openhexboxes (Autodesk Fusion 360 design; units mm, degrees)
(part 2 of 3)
sketch "Skizze8" plane through (0, 0, 50) normal (0, 0, 1) x axis (1, 0, 0)
  line L1 (-23.6181, -113.2077) -> (-22.5788, -113.2077)
  line L2 (-20.4382, -105) -> (-24.3975, -111.8577)
  line L3 (-24.3975, -98.1423) -> (-20.4382, -105)
  line L4 (-25.7831, -99.0423) -> (-25.2635, -98.1423)
  line L5 (-33.342, -88.65) -> (-27.342, -99.0423)
  line L6 (-28.0592, -87.3) -> (-32.5626, -87.3)
  line L7 (-33.6262, -76.1577) -> (-27.6262, -86.55)
  line L8 (-35.0119, -77.0577) -> (-34.4922, -76.1577)
  line L9 (-40.53, -70.2) -> (-36.5707, -77.0577)
  line L10 (-48.4486, -70.2) -> (-40.53, -70.2)
  line L11 (-48.362, -71.85) -> (-48.8816, -70.95)
  line L12 (-61.1414, -73.2) -> (-49.1414, -73.2)
  line L13 (-59.6692, -67.95) -> (-61.9208, -71.85)
  line L14 (-72.1022, -67.2) -> (-60.1022, -67.2)
  line L15 (-72.0156, -68.85) -> (-72.5352, -67.95)
  line L16 (-80.7136, -70.2) -> (-72.795, -70.2)
  line L17 (-84.6729, -77.0577) -> (-80.7136, -70.2)
  line L18 (-83.2006, -77.8077) -> (-84.2398, -77.8077)
  line L19 (-88.4212, -89.55) -> (-82.4212, -79.1577)
  line L20 (-92.2317, -85.65) -> (-89.98, -89.55)
  line L21 (-99.0977, -96.0423) -> (-93.0977, -85.65)
  line L22 (-97.6255, -96.7923) -> (-98.6647, -96.7923)
  line L23 (-100.8054, -105) -> (-96.8461, -98.1423)
  line L24 (-96.8461, -111.8577) -> (-100.8054, -105)
  line L25 (-95.4604, -110.9577) -> (-95.98, -111.8577)
  line L26 (-87.9016, -121.35) -> (-93.9016, -110.9577)
  line L27 (-93.1843, -122.7) -> (-88.681, -122.7)
  line L28 (-87.6173, -133.8423) -> (-93.6173, -123.45)
  line L29 (-86.2317, -132.9423) -> (-86.7513, -133.8423)
  line L30 (-80.7136, -139.8) -> (-84.6729, -132.9423)
  line L31 (-72.795, -139.8) -> (-80.7136, -139.8)
  line L32 (-72.8816, -138.15) -> (-72.362, -139.05)
  line L33 (-60.1022, -136.8) -> (-72.1022, -136.8)
  line L34 (-61.5744, -142.05) -> (-59.3227, -138.15)
  line L35 (-49.1414, -142.8) -> (-61.1414, -142.8)
  line L36 (-49.228, -141.15) -> (-48.7084, -142.05)
  line L37 (-40.53, -139.8) -> (-48.4486, -139.8)
  line L38 (-36.5707, -132.9423) -> (-40.53, -139.8)
  line L39 (-38.0429, -132.1923) -> (-37.0037, -132.1923)
  line L40 (-32.8224, -120.45) -> (-38.8224, -130.8423)
  line L41 (-29.0119, -124.35) -> (-31.2635, -120.45)
  line L42 (-22.1458, -113.9577) -> (-28.1458, -124.35)
  line L43 (-100.8054, -105) -> (-20.4382, -105)
  line L44 (-80.7136, -139.8) -> (-40.53, -70.2)
  arc A1 centre (-23.6181, -112.3077) radius 0.9 clockwise from (-23.6181, -113.2077) to (-24.3975, -111.8577)
  arc A2 centre (-24.8305, -98.3923) radius 0.5 clockwise from (-25.2635, -98.1423) to (-24.3975, -98.1423)
  arc A3 centre (-26.5626, -98.5923) radius 0.9 clockwise from (-25.7831, -99.0423) to (-27.342, -99.0423)
  arc A4 centre (-32.5626, -88.2) radius 0.9 clockwise from (-33.342, -88.65) to (-32.5626, -87.3)
  arc A5 centre (-28.0592, -86.8) radius 0.5 clockwise from (-27.6262, -86.55) to (-28.0592, -87.3)
  arc A6 centre (-34.0592, -76.4077) radius 0.5 clockwise from (-34.4922, -76.1577) to (-33.6262, -76.1577)
  arc A7 centre (-35.7913, -76.6077) radius 0.9 clockwise from (-35.0119, -77.0577) to (-36.5707, -77.0577)
  arc A8 centre (-48.4486, -70.7) radius 0.5 clockwise from (-48.8816, -70.95) to (-48.4486, -70.2)
  arc A9 centre (-49.1414, -72.3) radius 0.9 clockwise from (-48.362, -71.85) to (-49.1414, -73.2)
  arc A10 centre (-61.1414, -72.3) radius 0.9 clockwise from (-61.1414, -73.2) to (-61.9208, -71.85)
  arc A11 centre (-60.1022, -67.7) radius 0.5 clockwise from (-60.1022, -67.2) to (-59.6692, -67.95)
  arc A12 centre (-72.1022, -67.7) radius 0.5 clockwise from (-72.5352, -67.95) to (-72.1022, -67.2)
  arc A13 centre (-72.795, -69.3) radius 0.9 clockwise from (-72.0156, -68.85) to (-72.795, -70.2)
  arc A14 centre (-84.2398, -77.3077) radius 0.5 clockwise from (-84.2398, -77.8077) to (-84.6729, -77.0577)
  arc A15 centre (-83.2006, -78.7077) radius 0.9 clockwise from (-83.2006, -77.8077) to (-82.4212, -79.1577)
  arc A16 centre (-89.2006, -89.1) radius 0.9 clockwise from (-88.4212, -89.55) to (-89.98, -89.55)
  arc A17 centre (-92.6647, -85.9) radius 0.5 clockwise from (-93.0977, -85.65) to (-92.2317, -85.65)
  arc A18 centre (-98.6647, -96.2923) radius 0.5 clockwise from (-98.6647, -96.7923) to (-99.0977, -96.0423)
  arc A19 centre (-97.6255, -97.6923) radius 0.9 clockwise from (-97.6255, -96.7923) to (-96.8461, -98.1423)
  arc A20 centre (-96.4131, -111.6077) radius 0.5 clockwise from (-95.98, -111.8577) to (-96.8461, -111.8577)
  arc A21 centre (-94.681, -111.4077) radius 0.9 clockwise from (-95.4604, -110.9577) to (-93.9016, -110.9577)
  arc A22 centre (-88.681, -121.8) radius 0.9 clockwise from (-87.9016, -121.35) to (-88.681, -122.7)
  arc A23 centre (-93.1843, -123.2) radius 0.5 clockwise from (-93.6173, -123.45) to (-93.1843, -122.7)
  arc A24 centre (-87.1843, -133.5923) radius 0.5 clockwise from (-86.7513, -133.8423) to (-87.6173, -133.8423)
  arc A25 centre (-85.4523, -133.3923) radius 0.9 clockwise from (-86.2317, -132.9423) to (-84.6729, -132.9423)
  arc A26 centre (-72.795, -139.3) radius 0.5 clockwise from (-72.362, -139.05) to (-72.795, -139.8)
  arc A27 centre (-72.1022, -137.7) radius 0.9 clockwise from (-72.8816, -138.15) to (-72.1022, -136.8)
  arc A28 centre (-60.1022, -137.7) radius 0.9 clockwise from (-60.1022, -136.8) to (-59.3227, -138.15)
  arc A29 centre (-61.1414, -142.3) radius 0.5 clockwise from (-61.1414, -142.8) to (-61.5744, -142.05)
  arc A30 centre (-49.1414, -142.3) radius 0.5 clockwise from (-48.7084, -142.05) to (-49.1414, -142.8)
  arc A31 centre (-48.4486, -140.7) radius 0.9 clockwise from (-49.228, -141.15) to (-48.4486, -139.8)
  arc A32 centre (-37.0037, -132.6923) radius 0.5 clockwise from (-37.0037, -132.1923) to (-36.5707, -132.9423)
  arc A33 centre (-38.0429, -131.2923) radius 0.9 clockwise from (-38.0429, -132.1923) to (-38.8224, -130.8423)
  arc A34 centre (-32.0429, -120.9) radius 0.9 clockwise from (-32.8224, -120.45) to (-31.2635, -120.45)
  arc A35 centre (-28.5788, -124.1) radius 0.5 clockwise from (-28.1458, -124.35) to (-29.0119, -124.35)
  arc A36 centre (-22.5788, -113.7077) radius 0.5 clockwise from (-22.5788, -113.2077) to (-22.1458, -113.9577)
  circle C1 centre (-60.6218, -105) radius 6.5
  circle C2 centre (-46.6218, -80.7513) radius 6.5
  circle C3 centre (-39.6218, -92.8756) radius 6.5
  circle C4 centre (-32.6218, -105) radius 6.5
  circle C5 centre (-60.6218, -80.7513) radius 6.5
  circle C6 centre (-53.6218, -92.8756) radius 6.5
  circle C7 centre (-46.6218, -105) radius 6.5
  circle C8 centre (-39.6218, -117.1244) radius 6.5
  circle C9 centre (-74.6218, -80.7513) radius 6.5
  circle C10 centre (-67.6218, -92.8756) radius 6.5
  circle C11 centre (-53.6218, -117.1244) radius 6.5
  circle C12 centre (-46.6218, -129.2487) radius 6.5
  circle C13 centre (-81.6218, -92.8756) radius 6.5
  circle C14 centre (-74.6218, -105) radius 6.5
  circle C15 centre (-67.6218, -117.1244) radius 6.5
  circle C16 centre (-60.6218, -129.2487) radius 6.5
  circle C17 centre (-88.6218, -105) radius 6.5
  circle C18 centre (-81.6218, -117.1244) radius 6.5
  circle C19 centre (-74.6218, -129.2487) radius 6.5
  dimension "d49" diameter C1 = 13
  dimension "d52" R-Pattern1-uDistance = 14
  dimension "d53" R-Pattern1-vDistance = 14
extrude "Extrusion7" sketch "Skizze8" profile of C1 C2 C3 C4 C5 C6 C7 C8 C9 C10 C11 C12 C13 C14 C15 C16 C17 C18 C19 blind -49
sketch "Skizze9" plane through (0, 0, 0) normal (0, 0, -1) x axis (-1, 0, 0)
  line L1 (22.5788, -113.2077) -> (23.6181, -113.2077)
  line L2 (28.1458, -124.35) -> (22.1458, -113.9577)
  line L3 (31.2635, -120.45) -> (29.0119, -124.35)
  line L4 (38.8224, -130.8423) -> (32.8224, -120.45)
  line L5 (37.0037, -132.1923) -> (38.0429, -132.1923)
  line L6 (40.53, -139.8) -> (36.5707, -132.9423)
  line L7 (48.4486, -139.8) -> (40.53, -139.8)
  line L8 (48.7084, -142.05) -> (49.228, -141.15)
  line L9 (61.1414, -142.8) -> (49.1414, -142.8)
  line L10 (59.3227, -138.15) -> (61.5744, -142.05)
  line L11 (72.1022, -136.8) -> (60.1022, -136.8)
  line L12 (72.362, -139.05) -> (72.8816, -138.15)
  line L13 (80.7136, -139.8) -> (72.795, -139.8)
  line L14 (84.6729, -132.9423) -> (80.7136, -139.8)
  line L15 (86.7513, -133.8423) -> (86.2317, -132.9423)
  line L16 (93.6173, -123.45) -> (87.6173, -133.8423)
  line L17 (88.681, -122.7) -> (93.1843, -122.7)
  line L18 (93.9016, -110.9577) -> (87.9016, -121.35)
  line L19 (95.98, -111.8577) -> (95.4604, -110.9577)
  line L20 (100.8054, -105) -> (96.8461, -111.8577)
  line L21 (96.8461, -98.1423) -> (100.8054, -105)
  line L22 (98.6647, -96.7923) -> (97.6255, -96.7923)
  line L23 (93.0977, -85.65) -> (99.0977, -96.0423)
  line L24 (89.98, -89.55) -> (92.2317, -85.65)
  line L25 (82.4212, -79.1577) -> (88.4212, -89.55)
  line L26 (84.2398, -77.8077) -> (83.2006, -77.8077)
  line L27 (80.7136, -70.2) -> (84.6729, -77.0577)
  line L28 (72.795, -70.2) -> (80.7136, -70.2)
  line L29 (72.5352, -67.95) -> (72.0156, -68.85)
  line L30 (60.1022, -67.2) -> (72.1022, -67.2)
  line L31 (61.9208, -71.85) -> (59.6692, -67.95)
  line L32 (49.1414, -73.2) -> (61.1414, -73.2)
  line L33 (48.8816, -70.95) -> (48.362, -71.85)
  line L34 (40.53, -70.2) -> (48.4486, -70.2)
  line L35 (36.5707, -77.0577) -> (40.53, -70.2)
  line L36 (34.4922, -76.1577) -> (35.0119, -77.0577)
  line L37 (27.6262, -86.55) -> (33.6262, -76.1577)
  line L38 (32.5626, -87.3) -> (28.0592, -87.3)
  line L39 (27.342, -99.0423) -> (33.342, -88.65)
  line L40 (25.2635, -98.1423) -> (25.7831, -99.0423)
  line L41 (20.4382, -105) -> (24.3975, -98.1423)
  line L42 (24.3975, -111.8577) -> (20.4382, -105)
  line L43 (49.1414, -75.2) -> (61.1414, -75.2)
  line L44 (63.6529, -70.85) -> (62.7002, -69.2)
  line L45 (62.7002, -69.2) -> (69.8967, -69.2)
  line L46 (72.795, -72.2) -> (79.5589, -72.2)
  line L47 (79.5589, -72.2) -> (81.8381, -76.1477)
  line L48 (80.6891, -80.1577) -> (86.6891, -90.55)
  line L49 (91.7121, -90.55) -> (92.6647, -88.9)
  line L50 (92.6647, -88.9) -> (96.263, -95.1323)
  line L51 (95.114, -99.1423) -> (98.496, -105)
  line L52 (98.496, -105) -> (96.2167, -108.9477)
  line L53 (92.1695, -109.9577) -> (86.1695, -120.35)
  line L54 (88.681, -124.7) -> (90.5863, -124.7)
  line L55 (90.5863, -124.7) -> (86.988, -130.9323)
  line L56 (82.9408, -131.9423) -> (79.5589, -137.8)
  line L57 (79.5589, -137.8) -> (75.0004, -137.8)
  line L58 (72.1022, -134.8) -> (60.1022, -134.8)
  line L59 (57.5907, -139.15) -> (58.5433, -140.8)
  line L60 (58.5433, -140.8) -> (51.3468, -140.8)
  line L61 (48.4486, -137.8) -> (41.6847, -137.8)
  line L62 (41.6847, -137.8) -> (39.4055, -133.8523)
  line L63 (40.5544, -129.8423) -> (34.5544, -119.45)
  line L64 (29.5315, -119.45) -> (28.5788, -121.1)
  line L65 (28.5788, -121.1) -> (24.9806, -114.8677)
  line L66 (26.1295, -110.8577) -> (22.7476, -105)
  line L67 (22.7476, -105) -> (25.0268, -101.0523)
  line L68 (29.074, -100.0423) -> (35.074, -89.65)
  line L69 (32.5626, -85.3) -> (30.6573, -85.3)
  line L70 (30.6573, -85.3) -> (34.2555, -79.0677)
  line L71 (38.3027, -78.0577) -> (41.6847, -72.2)
  line L72 (41.6847, -72.2) -> (46.2431, -72.2)
  line L73 (98.4809, -104.9739) -> (22.7627, -104.9739)
  line L74 (23.8872, -106.9739) -> (97.3563, -106.9739)
  line L75 (78.439, -137.8) -> (41.0062, -73.3752)
  line L76 (42.6364, -72.2) -> (80.1536, -136.7699)
  line L77 (41.1878, -136.9393) -> (77.5695, -72.2)
  line L78 (79.7133, -72.4675) -> (42.9983, -137.8)
  line L79 (79.7133, -72.4675) -> (80.1536, -136.7699)
  line L80 (78.439, -136.7699) -> (78.439, -137.8)
  line L81 (77.5695, -72.2) -> (78.439, -136.7699)
  line L82 (41.1878, -136.9393) -> (41.0062, -73.3752)
  line L83 (42.9983, -137.8) -> (42.6364, -72.2)
  line L84 (71.6862, -122.1969) -> (49.4992, -122.1497)
  line L85 (47.7981, -125.1765) -> (73.4492, -125.2311)
  line L86 (71.2684, -87.4949) -> (48.8416, -86.8605)
  line L87 (72.3835, -85.5105) -> (47.6506, -84.8108)
  arc A1 centre (22.5788, -113.7077) radius 0.5 clockwise from (22.1458, -113.9577) to (22.5788, -113.2077)
  arc A2 centre (28.5788, -124.1) radius 0.5 clockwise from (29.0119, -124.35) to (28.1458, -124.35)
  arc A3 centre (32.0429, -120.9) radius 0.9 clockwise from (31.2635, -120.45) to (32.8224, -120.45)
  arc A4 centre (38.0429, -131.2923) radius 0.9 clockwise from (38.8224, -130.8423) to (38.0429, -132.1923)
  arc A5 centre (37.0037, -132.6923) radius 0.5 clockwise from (36.5707, -132.9423) to (37.0037, -132.1923)
  arc A6 centre (48.4486, -140.7) radius 0.9 clockwise from (48.4486, -139.8) to (49.228, -141.15)
  arc A7 centre (49.1414, -142.3) radius 0.5 clockwise from (49.1414, -142.8) to (48.7084, -142.05)
  arc A8 centre (61.1414, -142.3) radius 0.5 clockwise from (61.5744, -142.05) to (61.1414, -142.8)
  arc A9 centre (60.1022, -137.7) radius 0.9 clockwise from (59.3227, -138.15) to (60.1022, -136.8)
  arc A10 centre (72.1022, -137.7) radius 0.9 clockwise from (72.1022, -136.8) to (72.8816, -138.15)
  arc A11 centre (72.795, -139.3) radius 0.5 clockwise from (72.795, -139.8) to (72.362, -139.05)
  arc A12 centre (85.4523, -133.3923) radius 0.9 clockwise from (84.6729, -132.9423) to (86.2317, -132.9423)
  arc A13 centre (87.1843, -133.5923) radius 0.5 clockwise from (87.6173, -133.8423) to (86.7513, -133.8423)
  arc A14 centre (93.1843, -123.2) radius 0.5 clockwise from (93.1843, -122.7) to (93.6173, -123.45)
  arc A15 centre (88.681, -121.8) radius 0.9 clockwise from (88.681, -122.7) to (87.9016, -121.35)
  arc A16 centre (94.681, -111.4077) radius 0.9 clockwise from (93.9016, -110.9577) to (95.4604, -110.9577)
  arc A17 centre (96.4131, -111.6077) radius 0.5 clockwise from (96.8461, -111.8577) to (95.98, -111.8577)
  arc A18 centre (97.6255, -97.6923) radius 0.9 clockwise from (96.8461, -98.1423) to (97.6255, -96.7923)
  arc A19 centre (98.6647, -96.2923) radius 0.5 clockwise from (99.0977, -96.0423) to (98.6647, -96.7923)
  arc A20 centre (92.6647, -85.9) radius 0.5 clockwise from (92.2317, -85.65) to (93.0977, -85.65)
  arc A21 centre (89.2006, -89.1) radius 0.9 clockwise from (89.98, -89.55) to (88.4212, -89.55)
  arc A22 centre (83.2006, -78.7077) radius 0.9 clockwise from (82.4212, -79.1577) to (83.2006, -77.8077)
  arc A23 centre (84.2398, -77.3077) radius 0.5 clockwise from (84.6729, -77.0577) to (84.2398, -77.8077)
  arc A24 centre (72.795, -69.3) radius 0.9 clockwise from (72.795, -70.2) to (72.0156, -68.85)
  arc A25 centre (72.1022, -67.7) radius 0.5 clockwise from (72.1022, -67.2) to (72.5352, -67.95)
  arc A26 centre (60.1022, -67.7) radius 0.5 clockwise from (59.6692, -67.95) to (60.1022, -67.2)
  arc A27 centre (61.1414, -72.3) radius 0.9 clockwise from (61.9208, -71.85) to (61.1414, -73.2)
  arc A28 centre (49.1414, -72.3) radius 0.9 clockwise from (49.1414, -73.2) to (48.362, -71.85)
  arc A29 centre (48.4486, -70.7) radius 0.5 clockwise from (48.4486, -70.2) to (48.8816, -70.95)
  arc A30 centre (35.7913, -76.6077) radius 0.9 clockwise from (36.5707, -77.0577) to (35.0119, -77.0577)
  arc A31 centre (34.0592, -76.4077) radius 0.5 clockwise from (33.6262, -76.1577) to (34.4922, -76.1577)
  arc A32 centre (28.0592, -86.8) radius 0.5 clockwise from (28.0592, -87.3) to (27.6262, -86.55)
  arc A33 centre (32.5626, -88.2) radius 0.9 clockwise from (32.5626, -87.3) to (33.342, -88.65)
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  dimension "d56" = 2
  dimension "d57" distance L73 L74 = 2
  dimension "d59" distance L77 L78 = 2
  dimension "d60" distance L75 L76 = 2
extrude "Extrusion8" sketch "Skizze9" blind -0.3
sketch "Skizze10" plane through (0, 0, 0) normal (0, 0, -1) x axis (-1, 0, 0)
  line L1 (-26.1295, -181.1577) -> (-25.6099, -182.0577)
  line L2 (-32.9956, -191.55) -> (-26.9956, -181.1577)
  line L3 (-28.0592, -192.3) -> (-32.5626, -192.3)
  line L4 (-33.2798, -204.0423) -> (-27.2798, -193.65)
  line L5 (-35.3583, -203.1423) -> (-34.8386, -204.0423)
  line L6 (-40.1836, -210) -> (-36.2243, -203.1423)
  line L7 (-36.2243, -216.8577) -> (-40.1836, -210)
  line L8 (-38.0429, -218.2077) -> (-37.0037, -218.2077)
  line L9 (-32.476, -229.35) -> (-38.476, -218.9577)
  line L10 (-29.3583, -225.45) -> (-31.6099, -229.35)
  line L11 (-21.7994, -235.8423) -> (-27.7994, -225.45)
  line L12 (-23.6181, -237.1923) -> (-22.5788, -237.1923)
  line L13 (-20.0918, -244.8) -> (-24.0511, -237.9423)
  line L14 (-12.1732, -244.8) -> (-20.0918, -244.8)
  line L15 (-11.9134, -247.05) -> (-11.3938, -246.15)
  line L16 (0.5196, -247.8) -> (-11.4804, -247.8)
  line L17 (-1.299, -243.15) -> (0.9526, -247.05)
  line L18 (11.4804, -241.8) -> (-0.5196, -241.8)
  line L19 (11.7402, -244.05) -> (12.2598, -243.15)
  line L20 (20.0918, -244.8) -> (12.1732, -244.8)
  line L21 (24.0511, -237.9423) -> (20.0918, -244.8)
  line L22 (26.1295, -238.8423) -> (25.6099, -237.9423)
  line L23 (32.9956, -228.45) -> (26.9956, -238.8423)
  line L24 (28.0592, -227.7) -> (32.5626, -227.7)
  line L25 (33.2798, -215.9577) -> (27.2798, -226.35)
  line L26 (35.3583, -216.8577) -> (34.8386, -215.9577)
  line L27 (40.1836, -210) -> (36.2243, -216.8577)
  line L28 (36.2243, -203.1423) -> (40.1836, -210)
  line L29 (38.0429, -201.7923) -> (37.0037, -201.7923)
  line L30 (32.476, -190.65) -> (38.476, -201.0423)
  line L31 (29.3583, -194.55) -> (31.6099, -190.65)
  line L32 (21.7994, -184.1577) -> (27.7994, -194.55)
  line L33 (23.6181, -182.8077) -> (22.5788, -182.8077)
  line L34 (20.0918, -175.2) -> (24.0511, -182.0577)
  line L35 (12.1732, -175.2) -> (20.0918, -175.2)
  line L36 (11.9134, -172.95) -> (11.3938, -173.85)
  line L37 (-0.5196, -172.2) -> (11.4804, -172.2)
  line L38 (1.299, -176.85) -> (-0.9526, -172.95)
  line L39 (-11.4804, -178.2) -> (0.5196, -178.2)
  line L40 (-11.7402, -175.95) -> (-12.2598, -176.85)
  line L41 (-20.0918, -175.2) -> (-12.1732, -175.2)
  line L42 (-24.0511, -182.0577) -> (-20.0918, -175.2)
  line L43 (31.5477, -214.9577) -> (25.5477, -225.35)
  line L44 (28.0592, -229.7) -> (29.9645, -229.7)
  line L45 (29.9645, -229.7) -> (26.3662, -235.9323)
  line L46 (22.319, -236.9423) -> (18.9371, -242.8)
  line L47 (18.9371, -242.8) -> (14.3787, -242.8)
  line L48 (11.4804, -239.8) -> (-0.5196, -239.8)
  line L49 (-3.0311, -244.15) -> (-2.0785, -245.8)
  line L50 (-2.0785, -245.8) -> (-9.2749, -245.8)
  line L51 (-12.1732, -242.8) -> (-18.9371, -242.8)
  line L52 (-18.9371, -242.8) -> (-21.2163, -238.8523)
  line L53 (-20.0674, -234.8423) -> (-26.0674, -224.45)
  line L54 (-31.0903, -224.45) -> (-32.0429, -226.1)
  line L55 (-32.0429, -226.1) -> (-35.6412, -219.8677)
  line L56 (-34.4922, -215.8577) -> (-37.8742, -210)
  line L57 (-37.8742, -210) -> (-35.595, -206.0523)
  line L58 (-31.5477, -205.0423) -> (-25.5477, -194.65)
  line L59 (-28.0592, -190.3) -> (-29.9645, -190.3)
  line L60 (-29.9645, -190.3) -> (-26.3662, -184.0677)
  line L61 (-22.319, -183.0577) -> (-18.9371, -177.2)
  line L62 (-18.9371, -177.2) -> (-14.3787, -177.2)
  line L63 (-11.4804, -180.2) -> (0.5196, -180.2)
  line L64 (3.0311, -175.85) -> (2.0785, -174.2)
  line L65 (2.0785, -174.2) -> (9.2749, -174.2)
  line L66 (12.1732, -177.2) -> (18.9371, -177.2)
  line L67 (18.9371, -177.2) -> (21.2163, -181.1477)
  line L68 (20.0674, -185.1577) -> (26.0674, -195.55)
  line L69 (31.0903, -195.55) -> (32.0429, -193.9)
  line L70 (32.0429, -193.9) -> (35.6412, -200.1323)
  line L71 (34.4922, -204.1423) -> (37.8742, -210)
  line L72 (37.8742, -210) -> (35.595, -213.9477)
  arc A1 centre (-26.5626, -181.4077) radius 0.5 clockwise from (-26.9956, -181.1577) to (-26.1295, -181.1577)
  arc A2 centre (-32.5626, -191.8) radius 0.5 clockwise from (-32.5626, -192.3) to (-32.9956, -191.55)
  arc A3 centre (-28.0592, -193.2) radius 0.9 clockwise from (-28.0592, -192.3) to (-27.2798, -193.65)
  arc A4 centre (-34.0592, -203.5923) radius 0.9 clockwise from (-33.2798, -204.0423) to (-34.8386, -204.0423)
  arc A5 centre (-35.7913, -203.3923) radius 0.5 clockwise from (-36.2243, -203.1423) to (-35.3583, -203.1423)
  arc A6 centre (-37.0037, -217.3077) radius 0.9 clockwise from (-36.2243, -216.8577) to (-37.0037, -218.2077)
  arc A7 centre (-38.0429, -218.7077) radius 0.5 clockwise from (-38.476, -218.9577) to (-38.0429, -218.2077)
  arc A8 centre (-32.0429, -229.1) radius 0.5 clockwise from (-31.6099, -229.35) to (-32.476, -229.35)
  arc A9 centre (-28.5788, -225.9) radius 0.9 clockwise from (-29.3583, -225.45) to (-27.7994, -225.45)
  arc A10 centre (-22.5788, -236.2923) radius 0.9 clockwise from (-21.7994, -235.8423) to (-22.5788, -237.1923)
  arc A11 centre (-23.6181, -237.6923) radius 0.5 clockwise from (-24.0511, -237.9423) to (-23.6181, -237.1923)
  arc A12 centre (-12.1732, -245.7) radius 0.9 clockwise from (-12.1732, -244.8) to (-11.3938, -246.15)
  arc A13 centre (-11.4804, -247.3) radius 0.5 clockwise from (-11.4804, -247.8) to (-11.9134, -247.05)
  arc A14 centre (0.5196, -247.3) radius 0.5 clockwise from (0.9526, -247.05) to (0.5196, -247.8)
  arc A15 centre (-0.5196, -242.7) radius 0.9 clockwise from (-1.299, -243.15) to (-0.5196, -241.8)
  arc A16 centre (11.4804, -242.7) radius 0.9 clockwise from (11.4804, -241.8) to (12.2598, -243.15)
  arc A17 centre (12.1732, -244.3) radius 0.5 clockwise from (12.1732, -244.8) to (11.7402, -244.05)
  arc A18 centre (24.8305, -238.3923) radius 0.9 clockwise from (24.0511, -237.9423) to (25.6099, -237.9423)
  arc A19 centre (26.5626, -238.5923) radius 0.5 clockwise from (26.9956, -238.8423) to (26.1295, -238.8423)
  arc A20 centre (32.5626, -228.2) radius 0.5 clockwise from (32.5626, -227.7) to (32.9956, -228.45)
  arc A21 centre (28.0592, -226.8) radius 0.9 clockwise from (28.0592, -227.7) to (27.2798, -226.35)
  arc A22 centre (34.0592, -216.4077) radius 0.9 clockwise from (33.2798, -215.9577) to (34.8386, -215.9577)
  arc A23 centre (35.7913, -216.6077) radius 0.5 clockwise from (36.2243, -216.8577) to (35.3583, -216.8577)
  arc A24 centre (37.0037, -202.6923) radius 0.9 clockwise from (36.2243, -203.1423) to (37.0037, -201.7923)
  arc A25 centre (38.0429, -201.2923) radius 0.5 clockwise from (38.476, -201.0423) to (38.0429, -201.7923)
  arc A26 centre (32.0429, -190.9) radius 0.5 clockwise from (31.6099, -190.65) to (32.476, -190.65)
  arc A27 centre (28.5788, -194.1) radius 0.9 clockwise from (29.3583, -194.55) to (27.7994, -194.55)
  arc A28 centre (22.5788, -183.7077) radius 0.9 clockwise from (21.7994, -184.1577) to (22.5788, -182.8077)
  arc A29 centre (23.6181, -182.3077) radius 0.5 clockwise from (24.0511, -182.0577) to (23.6181, -182.8077)
  arc A30 centre (12.1732, -174.3) radius 0.9 clockwise from (12.1732, -175.2) to (11.3938, -173.85)
  arc A31 centre (11.4804, -172.7) radius 0.5 clockwise from (11.4804, -172.2) to (11.9134, -172.95)
  arc A32 centre (-0.5196, -172.7) radius 0.5 clockwise from (-0.9526, -172.95) to (-0.5196, -172.2)
  arc A33 centre (0.5196, -177.3) radius 0.9 clockwise from (1.299, -176.85) to (0.5196, -178.2)
  arc A34 centre (-11.4804, -177.3) radius 0.9 clockwise from (-11.4804, -178.2) to (-12.2598, -176.85)
  arc A35 centre (-12.1732, -175.7) radius 0.5 clockwise from (-12.1732, -175.2) to (-11.7402, -175.95)
  arc A36 centre (-24.8305, -181.6077) radius 0.9 clockwise from (-24.0511, -182.0577) to (-25.6099, -182.0577)
  arc A37 centre (34.0592, -216.4077) radius 2.9 clockwise from (31.5477, -214.9577) to (35.595, -213.9477)
  arc A38 centre (28.0592, -226.8) radius 2.9 clockwise from (28.0592, -229.7) to (25.5477, -225.35)
  arc A39 centre (24.8305, -238.3923) radius 2.9 clockwise from (22.319, -236.9423) to (26.3662, -235.9323)
  arc A40 centre (11.4804, -242.7) radius 2.9 clockwise from (11.4804, -239.8) to (14.3787, -242.8)
  arc A41 centre (-0.5196, -242.7) radius 2.9 clockwise from (-3.0311, -244.15) to (-0.5196, -239.8)
  arc A42 centre (-12.1732, -245.7) radius 2.9 clockwise from (-12.1732, -242.8) to (-9.2749, -245.8)
  arc A43 centre (-22.5788, -236.2923) radius 2.9 clockwise from (-20.0674, -234.8423) to (-21.2163, -238.8523)
  arc A44 centre (-28.5788, -225.9) radius 2.9 clockwise from (-31.0903, -224.45) to (-26.0674, -224.45)
  arc A45 centre (-37.0037, -217.3077) radius 2.9 clockwise from (-34.4922, -215.8577) to (-35.6412, -219.8677)
  arc A46 centre (-34.0592, -203.5923) radius 2.9 clockwise from (-31.5477, -205.0423) to (-35.595, -206.0523)
  arc A47 centre (-28.0592, -193.2) radius 2.9 clockwise from (-28.0592, -190.3) to (-25.5477, -194.65)
  arc A48 centre (-24.8305, -181.6077) radius 2.9 clockwise from (-22.319, -183.0577) to (-26.3662, -184.0677)
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  dimension "d63" = 2
extrude "Extrusion9" sketch "Skizze10" blind -0.3
offset_faces "Flächen versetzen4" distance -20
copy_paste_bodies "Körper kopieren/einfügen6"
move "Verschieben7"
sketch "Skizze11" plane through (0, 0, 30) normal (0, 0, 1) x axis (1, 0, 0)
  line L1 (-23.6181, -183.2077) -> (-22.5788, -183.2077)
  line L2 (-20.4382, -175) -> (-24.3975, -181.8577)
  line L3 (-24.3975, -168.1423) -> (-20.4382, -175)
  line L4 (-25.7831, -169.0423) -> (-25.2635, -168.1423)
  line L5 (-33.342, -158.65) -> (-27.342, -169.0423)
  line L6 (-28.0592, -157.3) -> (-32.5626, -157.3)
  line L7 (-33.6262, -146.1577) -> (-27.6262, -156.55)
  line L8 (-35.0119, -147.0577) -> (-34.4922, -146.1577)
  line L9 (-40.53, -140.2) -> (-36.5707, -147.0577)
  line L10 (-48.4486, -140.2) -> (-40.53, -140.2)
  line L11 (-48.362, -141.85) -> (-48.8816, -140.95)
  line L12 (-61.1414, -143.2) -> (-49.1414, -143.2)
  line L13 (-59.6692, -137.95) -> (-61.9208, -141.85)
  line L14 (-72.1022, -137.2) -> (-60.1022, -137.2)
  line L15 (-72.0156, -138.85) -> (-72.5352, -137.95)
  line L16 (-80.7136, -140.2) -> (-72.795, -140.2)
  line L17 (-84.6729, -147.0577) -> (-80.7136, -140.2)
  line L18 (-83.2006, -147.8077) -> (-84.2398, -147.8077)
  line L19 (-88.4212, -159.55) -> (-82.4212, -149.1577)
  line L20 (-92.2317, -155.65) -> (-89.98, -159.55)
  line L21 (-99.0977, -166.0423) -> (-93.0977, -155.65)
  line L22 (-97.6255, -166.7923) -> (-98.6647, -166.7923)
  line L23 (-100.8054, -175) -> (-96.8461, -168.1423)
  line L24 (-96.8461, -181.8577) -> (-100.8054, -175)
  line L25 (-95.4604, -180.9577) -> (-95.98, -181.8577)
  line L26 (-87.9016, -191.35) -> (-93.9016, -180.9577)
  line L27 (-93.1843, -192.7) -> (-88.681, -192.7)
  line L28 (-87.6173, -203.8423) -> (-93.6173, -193.45)
  line L29 (-86.2317, -202.9423) -> (-86.7513, -203.8423)
  line L30 (-80.7136, -209.8) -> (-84.6729, -202.9423)
  line L31 (-72.795, -209.8) -> (-80.7136, -209.8)
  line L32 (-72.8816, -208.15) -> (-72.362, -209.05)
  line L33 (-60.1022, -206.8) -> (-72.1022, -206.8)
  line L34 (-61.5744, -212.05) -> (-59.3227, -208.15)
  line L35 (-49.1414, -212.8) -> (-61.1414, -212.8)
  line L36 (-49.228, -211.15) -> (-48.7084, -212.05)
  line L37 (-40.53, -209.8) -> (-48.4486, -209.8)
  line L38 (-36.5707, -202.9423) -> (-40.53, -209.8)
  line L39 (-38.0429, -202.1923) -> (-37.0037, -202.1923)
  line L40 (-32.8224, -190.45) -> (-38.8224, -200.8423)
  line L41 (-29.0119, -194.35) -> (-31.2635, -190.45)
  line L42 (-22.1458, -183.9577) -> (-28.1458, -194.35)
  line L43 (-96.4175, -175) -> (-78.5196, -144)
  line L44 (-78.5196, -206) -> (-96.4175, -175)
  line L45 (-42.7239, -206) -> (-78.5196, -206)
  line L46 (-24.8261, -175) -> (-42.7239, -206)
  line L47 (-42.7239, -144) -> (-24.8261, -175)
  line L48 (-78.5196, -144) -> (-42.7239, -144)
  line L49 (-80.7136, -209.8) -> (-40.53, -140.2)
  line L50 (-40.53, -209.8) -> (-80.7136, -140.2)
  line L51 (-31.1769, -164) -> (-90.0666, -164)
  line L52 (-31.1769, -186) -> (-90.0666, -186)
  line L53 (-30.715, -164.8) -> (-90.5285, -164.8)
  line L54 (-90.5285, -185.2) -> (-30.715, -185.2)
  arc A1 centre (-23.6181, -182.3077) radius 0.9 clockwise from (-23.6181, -183.2077) to (-24.3975, -181.8577)
  arc A2 centre (-24.8305, -168.3923) radius 0.5 clockwise from (-25.2635, -168.1423) to (-24.3975, -168.1423)
  arc A3 centre (-26.5626, -168.5923) radius 0.9 clockwise from (-25.7831, -169.0423) to (-27.342, -169.0423)
  arc A4 centre (-32.5626, -158.2) radius 0.9 clockwise from (-33.342, -158.65) to (-32.5626, -157.3)
  arc A5 centre (-28.0592, -156.8) radius 0.5 clockwise from (-27.6262, -156.55) to (-28.0592, -157.3)
  arc A6 centre (-34.0592, -146.4077) radius 0.5 clockwise from (-34.4922, -146.1577) to (-33.6262, -146.1577)
  arc A7 centre (-35.7913, -146.6077) radius 0.9 clockwise from (-35.0119, -147.0577) to (-36.5707, -147.0577)
  arc A8 centre (-48.4486, -140.7) radius 0.5 clockwise from (-48.8816, -140.95) to (-48.4486, -140.2)
  arc A9 centre (-49.1414, -142.3) radius 0.9 clockwise from (-48.362, -141.85) to (-49.1414, -143.2)
  arc A10 centre (-61.1414, -142.3) radius 0.9 clockwise from (-61.1414, -143.2) to (-61.9208, -141.85)
  arc A11 centre (-60.1022, -137.7) radius 0.5 clockwise from (-60.1022, -137.2) to (-59.6692, -137.95)
  arc A12 centre (-72.1022, -137.7) radius 0.5 clockwise from (-72.5352, -137.95) to (-72.1022, -137.2)
  arc A13 centre (-72.795, -139.3) radius 0.9 clockwise from (-72.0156, -138.85) to (-72.795, -140.2)
  arc A14 centre (-84.2398, -147.3077) radius 0.5 clockwise from (-84.2398, -147.8077) to (-84.6729, -147.0577)
  arc A15 centre (-83.2006, -148.7077) radius 0.9 clockwise from (-83.2006, -147.8077) to (-82.4212, -149.1577)
  arc A16 centre (-89.2006, -159.1) radius 0.9 clockwise from (-88.4212, -159.55) to (-89.98, -159.55)
  arc A17 centre (-92.6647, -155.9) radius 0.5 clockwise from (-93.0977, -155.65) to (-92.2317, -155.65)
  arc A18 centre (-98.6647, -166.2923) radius 0.5 clockwise from (-98.6647, -166.7923) to (-99.0977, -166.0423)
  arc A19 centre (-97.6255, -167.6923) radius 0.9 clockwise from (-97.6255, -166.7923) to (-96.8461, -168.1423)
  arc A20 centre (-96.4131, -181.6077) radius 0.5 clockwise from (-95.98, -181.8577) to (-96.8461, -181.8577)
  arc A21 centre (-94.681, -181.4077) radius 0.9 clockwise from (-95.4604, -180.9577) to (-93.9016, -180.9577)
  arc A22 centre (-88.681, -191.8) radius 0.9 clockwise from (-87.9016, -191.35) to (-88.681, -192.7)
  arc A23 centre (-93.1843, -193.2) radius 0.5 clockwise from (-93.6173, -193.45) to (-93.1843, -192.7)
  arc A24 centre (-87.1843, -203.5923) radius 0.5 clockwise from (-86.7513, -203.8423) to (-87.6173, -203.8423)
  arc A25 centre (-85.4523, -203.3923) radius 0.9 clockwise from (-86.2317, -202.9423) to (-84.6729, -202.9423)
  arc A26 centre (-72.795, -209.3) radius 0.5 clockwise from (-72.362, -209.05) to (-72.795, -209.8)
  arc A27 centre (-72.1022, -207.7) radius 0.9 clockwise from (-72.8816, -208.15) to (-72.1022, -206.8)
  arc A28 centre (-60.1022, -207.7) radius 0.9 clockwise from (-60.1022, -206.8) to (-59.3227, -208.15)
  arc A29 centre (-61.1414, -212.3) radius 0.5 clockwise from (-61.1414, -212.8) to (-61.5744, -212.05)
  arc A30 centre (-49.1414, -212.3) radius 0.5 clockwise from (-48.7084, -212.05) to (-49.1414, -212.8)
  arc A31 centre (-48.4486, -210.7) radius 0.9 clockwise from (-49.228, -211.15) to (-48.4486, -209.8)
  arc A32 centre (-37.0037, -202.6923) radius 0.5 clockwise from (-37.0037, -202.1923) to (-36.5707, -202.9423)
  arc A33 centre (-38.0429, -201.2923) radius 0.9 clockwise from (-38.0429, -202.1923) to (-38.8224, -200.8423)
  arc A34 centre (-32.0429, -190.9) radius 0.9 clockwise from (-32.8224, -190.45) to (-31.2635, -190.45)
  arc A35 centre (-28.5788, -194.1) radius 0.5 clockwise from (-28.1458, -194.35) to (-29.0119, -194.35)
  arc A36 centre (-22.5788, -183.7077) radius 0.5 clockwise from (-22.5788, -183.2077) to (-22.1458, -183.9577)
  dimension "d67" distance L19 L43 = 0.8
  dimension "d68" distance L45 L52 = 20 (= "d69")
  dimension "d69" distance L48 L51 = 20
  dimension "d70" = 24
  dimension "d71" distance L52 L54 = 0.8
  dimension "d72" distance L51 L53 = 0.8
extrude "Extrusion10" sketch "Skizze11" profile of L43 L44 L45 L46 L47 L48 L51 L52 L53 L54 blind -27
offset_faces "Flächen versetzen5" distance -10
sketch "Skizze12" plane through (0, -164.8, 0) normal (0, -1, 0) x axis (1, 0, 0)
  line L1 (-90.5285, 20) -> (-30.715, 20)
  line L2 (-90.5285, 3) -> (-90.5285, 20)
  line L3 (-30.715, 3) -> (-90.5285, 3)
  line L4 (-30.715, 20) -> (-30.715, 3)
  line L5 (-97.6255, 50) -> (-97.6255, 0)
  line L6 (-96.4175, 1.6742) -> (-96.4175, 20)
  line L7 (-25.7831, 30) -> (-25.7831, 0)
  line L8 (-25.7831, 1.6742) -> (-96.4175, 1.6742)
  line L9 (-25.7831, 1.6742) -> (-24.8261, 20)
  circle C1 centre (-60.6218, 49.1863) radius 46.1863
extrude "Extrusion11" sketch "Skizze12" profile of L2 L3 L4 C1 L6 L7 L8 blind 20.4
extrude "Extrusion12" of existing geometry blind -87
delete_face "Fläche löschen"
fillet "Abrundung2" radius 5
sketch "Skizze13" plane through (0, -164, 0) normal (0, 1, 0) x axis (-1, 0, 0)
  line L1 (31.1769, 20) -> (90.0666, 20)
  line L2 (31.1769, 3) -> (31.1769, 20)
  line L3 (90.0666, 3) -> (31.1769, 3)
  line L4 (90.0666, 20) -> (90.0666, 3)
  circle C1 centre (60.6218, 37) radius 34
extrude "Extrusion13" add sketch "Skizze13" profile of L2 L3 L4 C1 to an object taper 15
fillet "Abrundung3" radius 5
sketch "Skizze14" plane through (0, -186, 0) normal (0, -1, 0) x axis (1, 0, 0)
  line L1 (-90.0666, 20) -> (-31.1769, 20)
  line L2 (-90.0666, 3) -> (-90.0666, 20)
  line L3 (-31.1769, 3) -> (-90.0666, 3)
  line L4 (-31.1769, 20) -> (-31.1769, 3)
sketch "Skizze15" plane through (-60.6218, -186, 11.5) normal (0, -1, 0) x axis (1, 0, 0)
  line L1 (29.4449, -8.5) -> (-29.4449, -8.5)
  line L2 (29.4449, -8.5) -> (29.4449, 8.5)
  line L3 (-29.4449, -8.5) -> (-29.3583, 8.5)
  circle C1 centre (0.0433, 25.5748) radius 34
  dimension "d84" diameter C1 = 68
sketch "Skizze17" plane through (-60.6218, -186, 11.5) normal (0, -1, 0) x axis (1, 0, 0)
  line L1 (29.4449, -8.5) -> (-29.4449, -8.5)
  circle C1 centre (0, 25.5) radius 34
extrude "Extrusion16" new body of existing geometry blind 17
extrude "Extrusion17" sketch "Skizze17" profile of C1 blind 20 taper -15
combine "Kombinieren1"
fillet "Abrundung4" radius 5
sketch "Skizze18" plane through (0, 0, 0) normal (0, 0, -1) x axis (-1, 0, 0)
  line L1 (22.5788, -183.2077) -> (23.6181, -183.2077)
  line L2 (28.1458, -194.35) -> (22.1458, -183.9577)
  line L3 (31.2635, -190.45) -> (29.0119, -194.35)
  line L4 (38.8224, -200.8423) -> (32.8224, -190.45)
  line L5 (37.0037, -202.1923) -> (38.0429, -202.1923)
  line L6 (40.53, -209.8) -> (36.5707, -202.9423)
  line L7 (48.4486, -209.8) -> (40.53, -209.8)
  line L8 (48.7084, -212.05) -> (49.228, -211.15)
  line L9 (61.1414, -212.8) -> (49.1414, -212.8)
  line L10 (59.3227, -208.15) -> (61.5744, -212.05)
  line L11 (72.1022, -206.8) -> (60.1022, -206.8)
  line L12 (72.362, -209.05) -> (72.8816, -208.15)
  line L13 (80.7136, -209.8) -> (72.795, -209.8)
  line L14 (84.6729, -202.9423) -> (80.7136, -209.8)
  line L15 (86.7513, -203.8423) -> (86.2317, -202.9423)
  line L16 (93.6173, -193.45) -> (87.6173, -203.8423)
  line L17 (88.681, -192.7) -> (93.1843, -192.7)
  line L18 (93.9016, -180.9577) -> (87.9016, -191.35)
  line L19 (95.98, -181.8577) -> (95.4604, -180.9577)
  line L20 (100.8054, -175) -> (96.8461, -181.8577)
  line L21 (96.8461, -168.1423) -> (100.8054, -175)
  line L22 (98.6647, -166.7923) -> (97.6255, -166.7923)
  line L23 (93.0977, -155.65) -> (99.0977, -166.0423)
  line L24 (89.98, -159.55) -> (92.2317, -155.65)
  line L25 (82.4212, -149.1577) -> (88.4212, -159.55)
  line L26 (84.2398, -147.8077) -> (83.2006, -147.8077)
  line L27 (80.7136, -140.2) -> (84.6729, -147.0577)
  line L28 (72.795, -140.2) -> (80.7136, -140.2)
  line L29 (72.5352, -137.95) -> (72.0156, -138.85)
  line L30 (60.1022, -137.2) -> (72.1022, -137.2)
  line L31 (61.9208, -141.85) -> (59.6692, -137.95)
  line L32 (49.1414, -143.2) -> (61.1414, -143.2)
  line L33 (48.8816, -140.95) -> (48.362, -141.85)
  line L34 (40.53, -140.2) -> (48.4486, -140.2)
  line L35 (36.5707, -147.0577) -> (40.53, -140.2)
  line L36 (34.4922, -146.1577) -> (35.0119, -147.0577)
  line L37 (27.6262, -156.55) -> (33.6262, -146.1577)
  line L38 (32.5626, -157.3) -> (28.0592, -157.3)
  line L39 (27.342, -169.0423) -> (33.342, -158.65)
  line L40 (25.2635, -168.1423) -> (25.7831, -169.0423)
  line L41 (20.4382, -175) -> (24.3975, -168.1423)
  line L42 (24.3975, -181.8577) -> (20.4382, -175)
  arc A1 centre (22.5788, -183.7077) radius 0.5 clockwise from (22.1458, -183.9577) to (22.5788, -183.2077)
  arc A2 centre (28.5788, -194.1) radius 0.5 clockwise from (29.0119, -194.35) to (28.1458, -194.35)
  arc A3 centre (32.0429, -190.9) radius 0.9 clockwise from (31.2635, -190.45) to (32.8224, -190.45)
  arc A4 centre (38.0429, -201.2923) radius 0.9 clockwise from (38.8224, -200.8423) to (38.0429, -202.1923)
  arc A5 centre (37.0037, -202.6923) radius 0.5 clockwise from (36.5707, -202.9423) to (37.0037, -202.1923)
  arc A6 centre (48.4486, -210.7) radius 0.9 clockwise from (48.4486, -209.8) to (49.228, -211.15)
  arc A7 centre (49.1414, -212.3) radius 0.5 clockwise from (49.1414, -212.8) to (48.7084, -212.05)
  arc A8 centre (61.1414, -212.3) radius 0.5 clockwise from (61.5744, -212.05) to (61.1414, -212.8)
  arc A9 centre (60.1022, -207.7) radius 0.9 clockwise from (59.3227, -208.15) to (60.1022, -206.8)
  arc A10 centre (72.1022, -207.7) radius 0.9 clockwise from (72.1022, -206.8) to (72.8816, -208.15)
  arc A11 centre (72.795, -209.3) radius 0.5 clockwise from (72.795, -209.8) to (72.362, -209.05)
  arc A12 centre (85.4523, -203.3923) radius 0.9 clockwise from (84.6729, -202.9423) to (86.2317, -202.9423)
  arc A13 centre (87.1843, -203.5923) radius 0.5 clockwise from (87.6173, -203.8423) to (86.7513, -203.8423)
  arc A14 centre (93.1843, -193.2) radius 0.5 clockwise from (93.1843, -192.7) to (93.6173, -193.45)
  arc A15 centre (88.681, -191.8) radius 0.9 clockwise from (88.681, -192.7) to (87.9016, -191.35)
  arc A16 centre (94.681, -181.4077) radius 0.9 clockwise from (93.9016, -180.9577) to (95.4604, -180.9577)
  arc A17 centre (96.4131, -181.6077) radius 0.5 clockwise from (96.8461, -181.8577) to (95.98, -181.8577)
  arc A18 centre (97.6255, -167.6923) radius 0.9 clockwise from (96.8461, -168.1423) to (97.6255, -166.7923)
  arc A19 centre (98.6647, -166.2923) radius 0.5 clockwise from (99.0977, -166.0423) to (98.6647, -166.7923)
  arc A20 centre (92.6647, -155.9) radius 0.5 clockwise from (92.2317, -155.65) to (93.0977, -155.65)
  arc A21 centre (89.2006, -159.1) radius 0.9 clockwise from (89.98, -159.55) to (88.4212, -159.55)
  arc A22 centre (83.2006, -148.7077) radius 0.9 clockwise from (82.4212, -149.1577) to (83.2006, -147.8077)
  arc A23 centre (84.2398, -147.3077) radius 0.5 clockwise from (84.6729, -147.0577) to (84.2398, -147.8077)
  arc A24 centre (72.795, -139.3) radius 0.9 clockwise from (72.795, -140.2) to (72.0156, -138.85)
  arc A25 centre (72.1022, -137.7) radius 0.5 clockwise from (72.1022, -137.2) to (72.5352, -137.95)
  arc A26 centre (60.1022, -137.7) radius 0.5 clockwise from (59.6692, -137.95) to (60.1022, -137.2)
  arc A27 centre (61.1414, -142.3) radius 0.9 clockwise from (61.9208, -141.85) to (61.1414, -143.2)
  arc A28 centre (49.1414, -142.3) radius 0.9 clockwise from (49.1414, -143.2) to (48.362, -141.85)
  arc A29 centre (48.4486, -140.7) radius 0.5 clockwise from (48.4486, -140.2) to (48.8816, -140.95)
  arc A30 centre (35.7913, -146.6077) radius 0.9 clockwise from (36.5707, -147.0577) to (35.0119, -147.0577)
  arc A31 centre (34.0592, -146.4077) radius 0.5 clockwise from (33.6262, -146.1577) to (34.4922, -146.1577)
  arc A32 centre (28.0592, -156.8) radius 0.5 clockwise from (28.0592, -157.3) to (27.6262, -156.55)
  arc A33 centre (32.5626, -158.2) radius 0.9 clockwise from (32.5626, -157.3) to (33.342, -158.65)
  arc A34 centre (26.5626, -168.5923) radius 0.9 clockwise from (27.342, -169.0423) to (25.7831, -169.0423)
  arc A35 centre (24.8305, -168.3923) radius 0.5 clockwise from (24.3975, -168.1423) to (25.2635, -168.1423)
  arc A36 centre (23.6181, -182.3077) radius 0.9 clockwise from (24.3975, -181.8577) to (23.6181, -183.2077)
sketch "Skizze19" plane through (0, 0, 0) normal (0, 0, -1) x axis (1, 0, 0)
  line L1 (-22.5788, 183.2077) -> (-23.6181, 183.2077)
  line L2 (-28.1458, 194.35) -> (-22.1458, 183.9577)
  line L3 (-31.2635, 190.45) -> (-29.0119, 194.35)
  line L4 (-38.8224, 200.8423) -> (-32.8224, 190.45)
  line L5 (-37.0037, 202.1923) -> (-38.0429, 202.1923)
  line L6 (-40.53, 209.8) -> (-36.5707, 202.9423)
  line L7 (-48.4486, 209.8) -> (-40.53, 209.8)
  line L8 (-48.7084, 212.05) -> (-49.228, 211.15)
  line L9 (-61.1414, 212.8) -> (-49.1414, 212.8)
  line L10 (-59.3227, 208.15) -> (-61.5744, 212.05)
  line L11 (-72.1022, 206.8) -> (-60.1022, 206.8)
  line L12 (-72.362, 209.05) -> (-72.8816, 208.15)
  line L13 (-80.7136, 209.8) -> (-72.795, 209.8)
  line L14 (-84.6729, 202.9423) -> (-80.7136, 209.8)
  line L15 (-86.7513, 203.8423) -> (-86.2317, 202.9423)
  line L16 (-93.6173, 193.45) -> (-87.6173, 203.8423)
  line L17 (-88.681, 192.7) -> (-93.1843, 192.7)
  line L18 (-93.9016, 180.9577) -> (-87.9016, 191.35)
  line L19 (-95.98, 181.8577) -> (-95.4604, 180.9577)
  line L20 (-100.8054, 175) -> (-96.8461, 181.8577)
  line L21 (-96.8461, 168.1423) -> (-100.8054, 175)
  line L22 (-98.6647, 166.7923) -> (-97.6255, 166.7923)
  line L23 (-93.0977, 155.65) -> (-99.0977, 166.0423)
  line L24 (-89.98, 159.55) -> (-92.2317, 155.65)
  line L25 (-82.4212, 149.1577) -> (-88.4212, 159.55)
  line L26 (-84.2398, 147.8077) -> (-83.2006, 147.8077)
  line L27 (-80.7136, 140.2) -> (-84.6729, 147.0577)
  line L28 (-72.795, 140.2) -> (-80.7136, 140.2)
  line L29 (-72.5352, 137.95) -> (-72.0156, 138.85)
  line L30 (-60.1022, 137.2) -> (-72.1022, 137.2)
  line L31 (-61.9208, 141.85) -> (-59.6692, 137.95)
  line L32 (-49.1414, 143.2) -> (-61.1414, 143.2)
  line L33 (-48.8816, 140.95) -> (-48.362, 141.85)
  line L34 (-40.53, 140.2) -> (-48.4486, 140.2)
  line L35 (-36.5707, 147.0577) -> (-40.53, 140.2)
  line L36 (-34.4922, 146.1577) -> (-35.0119, 147.0577)
  line L37 (-27.6262, 156.55) -> (-33.6262, 146.1577)
  line L38 (-32.5626, 157.3) -> (-28.0592, 157.3)
  line L39 (-27.342, 169.0423) -> (-33.342, 158.65)
  line L40 (-25.2635, 168.1423) -> (-25.7831, 169.0423)
  line L41 (-20.4382, 175) -> (-24.3975, 168.1423)
  line L42 (-24.3975, 181.8577) -> (-20.4382, 175)
  line L43 (-40.208, 200.0423) -> (-34.208, 189.65)
  line L44 (-29.8779, 189.65) -> (-28.5788, 191.9)
  line L45 (-28.5788, 191.9) -> (-24.4098, 184.679)
  line L46 (-25.7831, 181.0577) -> (-22.2857, 175)
  line L47 (-22.2857, 175) -> (-24.9048, 170.4636)
  line L48 (-28.7276, 169.8423) -> (-34.7276, 159.45)
  line L49 (-32.5626, 155.7) -> (-29.9645, 155.7)
  line L50 (-29.9645, 155.7) -> (-34.1335, 148.479)
  line L51 (-37.9563, 147.8577) -> (-41.4537, 141.8)
  line L52 (-41.4537, 141.8) -> (-46.6919, 141.8)
  line L53 (-49.1414, 144.8) -> (-61.1414, 144.8)
  line L54 (-63.3065, 141.05) -> (-62.0074, 138.8)
  line L55 (-62.0074, 138.8) -> (-70.3455, 138.8)
  line L56 (-72.795, 141.8) -> (-79.7898, 141.8)
  line L57 (-79.7898, 141.8) -> (-82.4089, 146.3364)
  line L58 (-81.0356, 149.9577) -> (-87.0356, 160.35)
  line L59 (-91.3657, 160.35) -> (-92.6647, 158.1)
  line L60 (-92.6647, 158.1) -> (-96.8338, 165.321)
  line L61 (-95.4604, 168.9423) -> (-98.9578, 175)
  line L62 (-98.9578, 175) -> (-96.3388, 179.5364)
  line L63 (-92.5159, 180.1577) -> (-86.5159, 190.55)
  line L64 (-88.681, 194.3) -> (-91.2791, 194.3)
  line L65 (-91.2791, 194.3) -> (-87.11, 201.521)
  line L66 (-83.2872, 202.1423) -> (-79.7898, 208.2)
  line L67 (-79.7898, 208.2) -> (-74.5517, 208.2)
  line L68 (-72.1022, 205.2) -> (-60.1022, 205.2)
  line L69 (-57.9371, 208.95) -> (-59.2361, 211.2)
  line L70 (-59.2361, 211.2) -> (-50.8981, 211.2)
  line L71 (-48.4486, 208.2) -> (-41.4537, 208.2)
  line L72 (-41.4537, 208.2) -> (-38.8347, 203.6636)
  arc A1 centre (-22.5788, 183.7077) radius 0.5 clockwise from (-22.1458, 183.9577) to (-22.5788, 183.2077)
  arc A2 centre (-28.5788, 194.1) radius 0.5 clockwise from (-29.0119, 194.35) to (-28.1458, 194.35)
  arc A3 centre (-32.0429, 190.9) radius 0.9 clockwise from (-31.2635, 190.45) to (-32.8224, 190.45)
  arc A4 centre (-38.0429, 201.2923) radius 0.9 clockwise from (-38.8224, 200.8423) to (-38.0429, 202.1923)
  arc A5 centre (-37.0037, 202.6923) radius 0.5 clockwise from (-36.5707, 202.9423) to (-37.0037, 202.1923)
  arc A6 centre (-48.4486, 210.7) radius 0.9 clockwise from (-48.4486, 209.8) to (-49.228, 211.15)
  arc A7 centre (-49.1414, 212.3) radius 0.5 clockwise from (-49.1414, 212.8) to (-48.7084, 212.05)
  arc A8 centre (-61.1414, 212.3) radius 0.5 clockwise from (-61.5744, 212.05) to (-61.1414, 212.8)
  arc A9 centre (-60.1022, 207.7) radius 0.9 clockwise from (-59.3227, 208.15) to (-60.1022, 206.8)
  arc A10 centre (-72.1022, 207.7) radius 0.9 clockwise from (-72.1022, 206.8) to (-72.8816, 208.15)
  arc A11 centre (-72.795, 209.3) radius 0.5 clockwise from (-72.795, 209.8) to (-72.362, 209.05)
  arc A12 centre (-85.4523, 203.3923) radius 0.9 clockwise from (-84.6729, 202.9423) to (-86.2317, 202.9423)
  arc A13 centre (-87.1843, 203.5923) radius 0.5 clockwise from (-87.6173, 203.8423) to (-86.7513, 203.8423)
  arc A14 centre (-93.1843, 193.2) radius 0.5 clockwise from (-93.1843, 192.7) to (-93.6173, 193.45)
  arc A15 centre (-88.681, 191.8) radius 0.9 clockwise from (-88.681, 192.7) to (-87.9016, 191.35)
  arc A16 centre (-94.681, 181.4077) radius 0.9 clockwise from (-93.9016, 180.9577) to (-95.4604, 180.9577)
  arc A17 centre (-96.4131, 181.6077) radius 0.5 clockwise from (-96.8461, 181.8577) to (-95.98, 181.8577)
  arc A18 centre (-97.6255, 167.6923) radius 0.9 clockwise from (-96.8461, 168.1423) to (-97.6255, 166.7923)
  arc A19 centre (-98.6647, 166.2923) radius 0.5 clockwise from (-99.0977, 166.0423) to (-98.6647, 166.7923)
  arc A20 centre (-92.6647, 155.9) radius 0.5 clockwise from (-92.2317, 155.65) to (-93.0977, 155.65)
  arc A21 centre (-89.2006, 159.1) radius 0.9 clockwise from (-89.98, 159.55) to (-88.4212, 159.55)
  arc A22 centre (-83.2006, 148.7077) radius 0.9 clockwise from (-82.4212, 149.1577) to (-83.2006, 147.8077)
  arc A23 centre (-84.2398, 147.3077) radius 0.5 clockwise from (-84.6729, 147.0577) to (-84.2398, 147.8077)
  arc A24 centre (-72.795, 139.3) radius 0.9 clockwise from (-72.795, 140.2) to (-72.0156, 138.85)
  arc A25 centre (-72.1022, 137.7) radius 0.5 clockwise from (-72.1022, 137.2) to (-72.5352, 137.95)
  arc A26 centre (-60.1022, 137.7) radius 0.5 clockwise from (-59.6692, 137.95) to (-60.1022, 137.2)
  arc A27 centre (-61.1414, 142.3) radius 0.9 clockwise from (-61.9208, 141.85) to (-61.1414, 143.2)
  arc A28 centre (-49.1414, 142.3) radius 0.9 clockwise from (-49.1414, 143.2) to (-48.362, 141.85)
  arc A29 centre (-48.4486, 140.7) radius 0.5 clockwise from (-48.4486, 140.2) to (-48.8816, 140.95)
  arc A30 centre (-35.7913, 146.6077) radius 0.9 clockwise from (-36.5707, 147.0577) to (-35.0119, 147.0577)
  arc A31 centre (-34.0592, 146.4077) radius 0.5 clockwise from (-33.6262, 146.1577) to (-34.4922, 146.1577)
  arc A32 centre (-28.0592, 156.8) radius 0.5 clockwise from (-28.0592, 157.3) to (-27.6262, 156.55)
  arc A33 centre (-32.5626, 158.2) radius 0.9 clockwise from (-32.5626, 157.3) to (-33.342, 158.65)
  arc A34 centre (-26.5626, 168.5923) radius 0.9 clockwise from (-27.342, 169.0423) to (-25.7831, 169.0423)
  arc A35 centre (-24.8305, 168.3923) radius 0.5 clockwise from (-24.3975, 168.1423) to (-25.2635, 168.1423)
  arc A36 centre (-23.6181, 182.3077) radius 0.9 clockwise from (-24.3975, 181.8577) to (-23.6181, 183.2077)
  arc A37 centre (-38.0429, 201.2923) radius 2.5 clockwise from (-40.208, 200.0423) to (-38.8347, 203.6636)
  arc A38 centre (-32.0429, 190.9) radius 2.5 clockwise from (-29.8779, 189.65) to (-34.208, 189.65)
  arc A39 centre (-23.6181, 182.3077) radius 2.5 clockwise from (-25.7831, 181.0577) to (-24.4098, 184.679)
  arc A40 centre (-26.5626, 168.5923) radius 2.5 clockwise from (-28.7276, 169.8423) to (-24.9048, 170.4636)
  arc A41 centre (-32.5626, 158.2) radius 2.5 clockwise from (-32.5626, 155.7) to (-34.7276, 159.45)
  arc A42 centre (-35.7913, 146.6077) radius 2.5 clockwise from (-37.9563, 147.8577) to (-34.1335, 148.479)
  arc A43 centre (-49.1414, 142.3) radius 2.5 clockwise from (-49.1414, 144.8) to (-46.6919, 141.8)
  arc A44 centre (-61.1414, 142.3) radius 2.5 clockwise from (-63.3065, 141.05) to (-61.1414, 144.8)
  arc A45 centre (-72.795, 139.3) radius 2.5 clockwise from (-72.795, 141.8) to (-70.3455, 138.8)
  arc A46 centre (-83.2006, 148.7077) radius 2.5 clockwise from (-81.0356, 149.9577) to (-82.4089, 146.3364)
  arc A47 centre (-89.2006, 159.1) radius 2.5 clockwise from (-91.3657, 160.35) to (-87.0356, 160.35)
  arc A48 centre (-97.6255, 167.6923) radius 2.5 clockwise from (-95.4604, 168.9423) to (-96.8338, 165.321)
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  dimension "d94" = 1.6
extrude "Extrusion18" cut sketch "Skizze19" against normal blind 0.3
sketch "Skizze20" plane through (0, -186, 0) normal (0, -1, 0) x axis (1, 0, 0)
sketch "Skizze21" plane through (0, 0, 0) normal (0, 0, -1) x axis (1, 0, 0)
